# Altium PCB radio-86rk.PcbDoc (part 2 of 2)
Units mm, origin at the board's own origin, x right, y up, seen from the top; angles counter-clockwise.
Board outline 258 x 185 mm, 2 copper layers (Top Layer, Top, Bottom Layer, Bottom); 104 components, 185 nets, 870 pads, 319 vias.
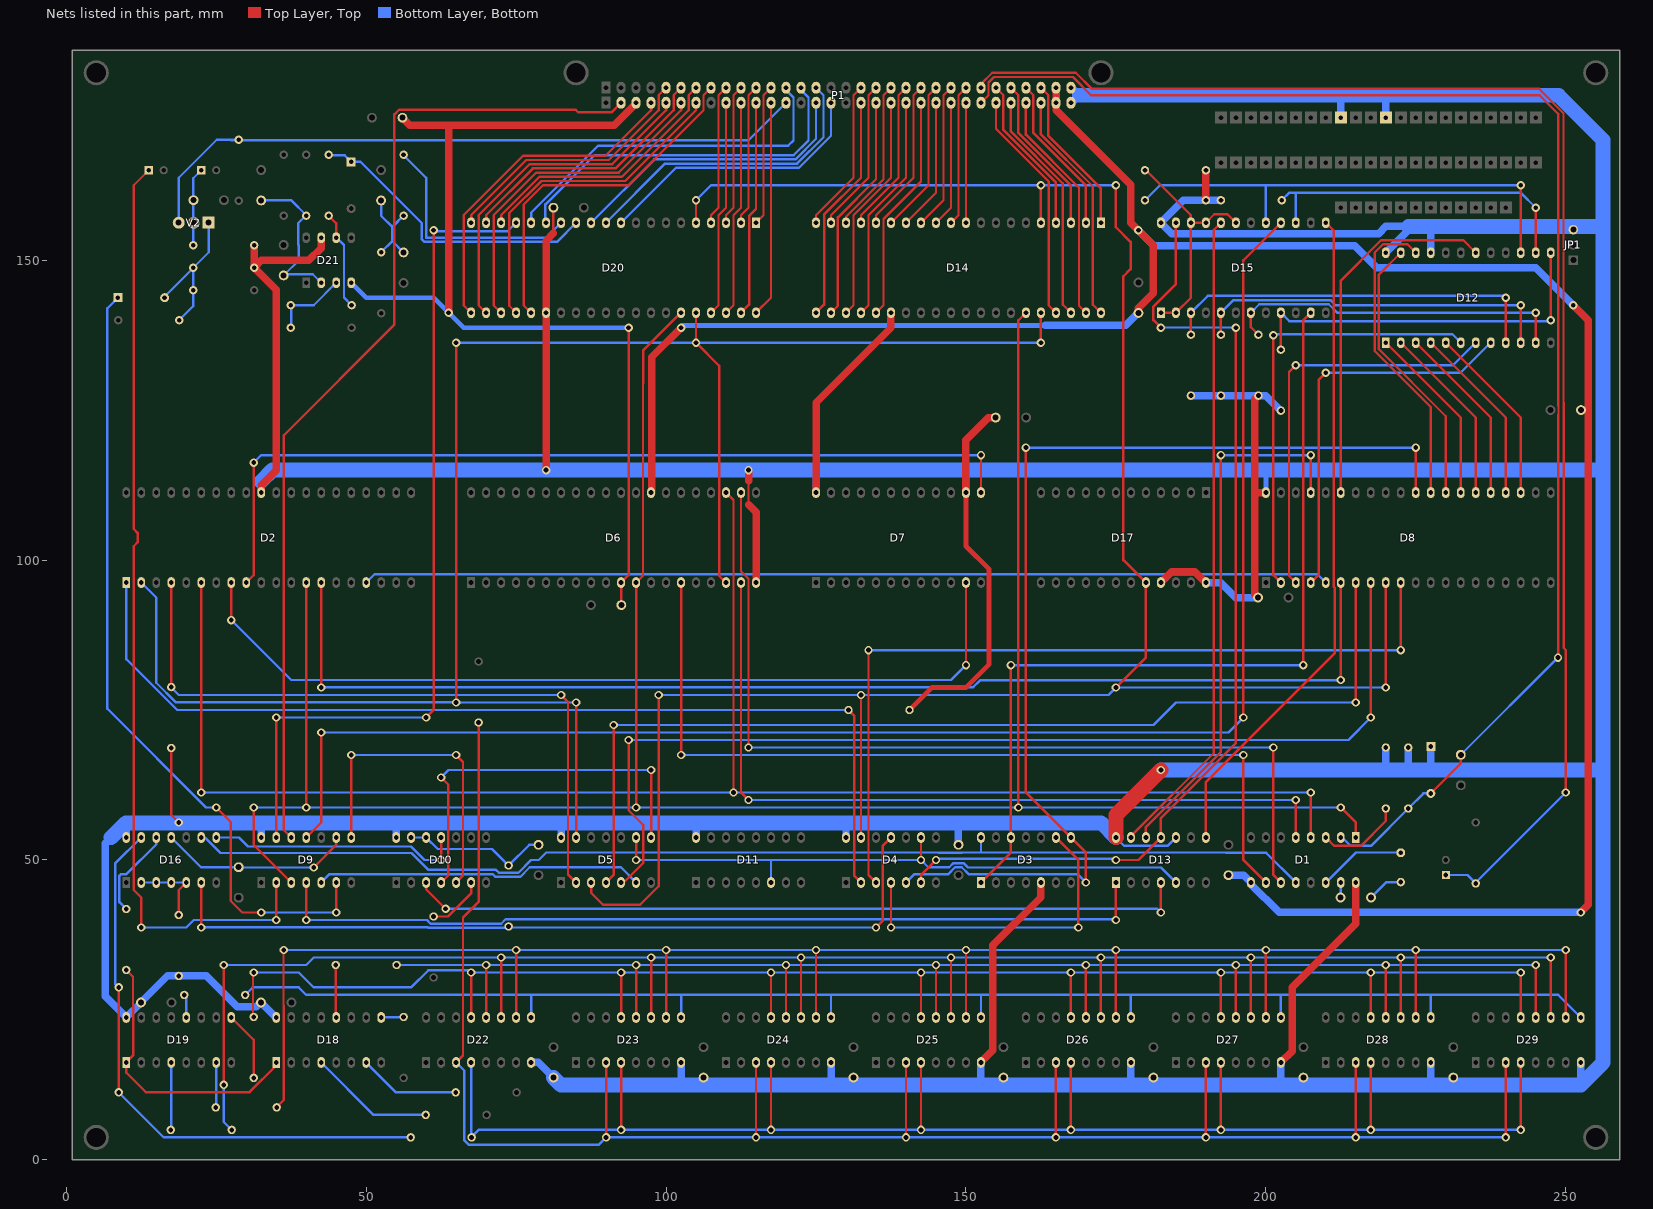
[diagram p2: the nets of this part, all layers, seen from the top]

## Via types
v1: diameter 1.4, hole 0.8, Top Layer, Top to Bottom Layer, Bottom, 318 vias
v2: diameter 1.4, hole 0.8, Top Layer, Top to Bottom Layer, Bottom, tented both sides, 1 vias

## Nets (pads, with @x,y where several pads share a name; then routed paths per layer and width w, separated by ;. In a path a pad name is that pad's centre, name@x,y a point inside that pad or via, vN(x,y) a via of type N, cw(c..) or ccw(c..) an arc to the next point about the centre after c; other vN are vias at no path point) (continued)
MA3: D22.12 D23.12 D24.12 D25.12 D26.12 D27.12 D28.12 D29.12 R24.1 | length 259.9
  Top Layer, Top w0.4: D22.12@70,23.75 v1(70,32.5) ; D23.12@95,23.75 v1(95,32.5) ; D24.12@120,23.75 v1(120,32.5) ; D25.12@145,23.75 v1(145,32.5) ; D26.12@170,23.75 v1(170,32.5) ; D27.12@195,23.75 v1(195,32.5) ; D28.12@220,23.75 v1(220,32.5) ; D29.12@245,23.75 v1(245,32.5)
  Bottom Layer, Bottom w0.4: R24.1@55.08,32.5 56.33,32.5 v1(70,32.5) v1(95,32.5) v1(120,32.5) v1(145,32.5) v1(170,32.5) v1(195,32.5) v1(220,32.5) v1(245,32.5)
MA4: D22.11 D23.11 D24.11 D25.11 D26.11 D27.11 D28.11 D29.11 R25.1 | length 329.8
  Top Layer, Top w0.4: v1(26.25,12.5) v1(26.25,32.5) ; D22.11@72.5,23.75 v1(72.5,33.75) ; D23.11@97.5,23.75 v1(97.5,33.75) ; D24.11@122.5,23.75 v1(122.5,33.75) ; D25.11@147.5,23.75 v1(147.5,33.75) ; D26.11@172.5,23.75 v1(172.5,33.75) ; D27.11@197.5,23.75 v1(197.5,33.75) ; D28.11@222.5,23.75 v1(222.5,33.75) ; D29.11@247.5,23.75 v1(247.5,33.75)
  Bottom Layer, Bottom w0.4: v1(26.25,12.5) 26.25,6.33 R25.1@27.58,5 ; v1(26.25,32.5) 40,32.5 41.25,33.75 v1(72.5,33.75) v1(97.5,33.75) v1(122.5,33.75) v1(147.5,33.75) v1(172.5,33.75) v1(197.5,33.75) v1(222.5,33.75) v1(247.5,33.75)
MA5: D22.10 D23.10 D24.10 D25.10 D26.10 D27.10 D28.10 D29.10 R26.1 | length 330.5
  Top Layer, Top w0.4: R26.1@35,8.75 36.25,10 36.25,25.666 36.215,25.701 36.215,34.965 v1(36.25,35) ; D22.10@75,23.75 v1(75,35) ; D23.10@100,23.75 v1(100,35) ; D24.10@125,23.75 v1(125,35) ; D25.10@150,23.75 v1(150,35) ; D26.10@175,23.75 v1(175,35) ; D27.10@200,23.75 v1(200,35) ; D28.10@225,23.75 v1(225,35) ; D29.10@250,23.75 v1(250,35)
  Bottom Layer, Bottom w0.4: v1(36.25,35) v1(75,35) v1(100,35) v1(125,35) v1(150,35) v1(175,35) v1(200,35) v1(225,35) v1(250,35)
MA6: D22.13 D23.13 D24.13 D25.13 D26.13 D27.13 D28.13 D29.13 R27.1 | length 281.2
  Top Layer, Top w0.4: R27.1@31.25,23.75 R27.1@31.25,23.83 31.135,23.945 31.135,31.135 v1(31.25,31.25) ; D22.13@67.5,23.75 v1(67.5,31.25) ; D23.13@92.5,23.75 v1(92.5,31.25) ; D24.13@117.5,23.75 v1(117.5,31.25) ; D25.13@142.5,23.75 v1(142.5,31.25) ; D26.13@167.5,23.75 v1(167.5,31.25) ; D27.13@192.5,23.75 v1(192.5,31.25) ; D28.13@217.5,23.75 v1(217.5,31.25) ; D29.13@242.5,23.75 v1(242.5,31.25)
  Bottom Layer, Bottom w0.4: v1(31.25,31.25) 38.75,31.25 41.25,28.75 57.501,28.75 60.371,31.62 67.13,31.62 v1(67.5,31.25) v1(92.5,31.25) v1(117.5,31.25) v1(142.5,31.25) v1(167.5,31.25) v1(192.5,31.25) v1(217.5,31.25) v1(242.5,31.25)
MA7: D22.9 D23.9 D24.9 D25.9 D26.9 D27.9 D28.9 D29.9 R34.1 | length 251.5
  Bottom Layer, Bottom w0.4: R34.1@29.83,27.5 31.08,28.75 38.749,28.75 40,27.499 77.5,27.499 ; D22.9@77.5,23.75 77.5,27.499 ; D23.9@102.5,23.75 102.5,27.499 ; D24.9@127.5,23.75 127.5,27.499 ; D25.9@152.5,23.75 152.5,27.499 ; D26.9@177.5,23.75 177.5,27.499 ; D27.9@202.5,23.75 202.5,27.499 ; D28.9@227.5,23.75 227.5,27.499 ; D29.9@252.5,23.75 248.751,27.499 227.5,27.499 ; 77.5,27.499 127.5,27.499 ; 127.5,27.499 152.5,27.499 ; 152.5,27.499 177.5,27.499 ; 177.5,27.499 202.5,27.499 ; 202.5,27.499 227.5,27.499
NetC3_1: C3.1 C4.2 R18.2 V2.C | length 13.1
  Bottom Layer, Bottom w0.4: R18.2@21.17,152.5 21.17,163.67 C3.1@22.5,165
NetC5_1: C5.1 C6.2 D21.2 R30.2 | length 26.8
  Bottom Layer, Bottom w0.4: C6.2@32.5,159.96 37.54,159.96 40,157.5 38.69,156.19 38.69,152.56 38.75,152.5 38.75,149.96 C5.1@36.44,147.65 ; C5.1@36.25,147.46 C5.1@36.44,147.65 ; D21.2@42.46,146.21 D21.2@42.48,146.19 ; D21.2@42.5,146.25 41.1,147.65 C5.1@36.44,147.65
NetC7_2: C7.2 C8.2 R32.2 R33.2 | length 18.2
  Bottom Layer, Bottom w0.4: R33.2@52.5,151.33 54.375,153.205 ; C8.2@52.5,159.96 52.5,157.42 54.375,155.545 ; 54.375,155.625 R32.2@56.25,157.5 ; C7.2@56.25,151.29 54.375,153.165 54.375,153.205 ; R32.2@56.25,157.42 54.375,155.545 ; 54.375,153.205 54.375,155.545
NetC26_1: C26.1 D9.2 | length 157.6
  Top Layer, Top w0.4: v1(12.5,38.75) 12.5,43.75 11.25,45 11.25,102.313 11.9,102.963 11.9,104.537 11.25,105.187 11.25,162.5 C26.1@13.75,165 ; v1(35,40) D9.2@35,46.25
  Bottom Layer, Bottom w0.4: v1(12.5,38.75) 20,38.75 21.25,40 v1(35,40)
NetC27_1: C27.1 D9.9 D16.11 | length 32.4
  Top Layer, Top w0.4: v1(41.25,48.75) 45,52.5 D9.9@45,53.75
  Bottom Layer, Bottom w0.4: D16.11@17.5,53.75 22.46,48.79 C27.1@28.75,48.79 28.79,48.75 v1(41.25,48.75)
NetC28_1: C28.1 D1.15 | length 2.5
  Bottom Layer, Bottom w0.4: C28.1@212.46,43.75 212.5,43.79 D1.15@212.5,46.25
NetC28_2: C28.2 Z1.2 | length 6
  Bottom Layer, Bottom w0.4: C28.2@217.54,43.75 220.1,46.31 Z1.2@222.5,46.31
NetC29_1: C29.1 D10.12 D10.13 R38.2 | length 24.6
  Bottom Layer, Bottom w0.4: D10.13@57.5,53.75 D10.12@60,53.75 61.925,51.825 71.005,51.825 R38.2@73.75,49.08 77.21,52.54 C29.1@78.75,52.54
NetD1_3: D1.3 R3.2 | length 14.6
  Top Layer, Top w0.4: D1.3@210,53.75 211.4,52.35 215.857,52.35 220,56.493 R3.2@220,58.59 R3.2@220,58.75
NetD1_10: D1.10 D6.15 | length 145.3
  Top Layer, Top w0.4: v1(102.5,67.5) D6.15@102.5,96.25 ; v1(196.25,67.5) 196.25,50 D1.10@200,46.25
  Bottom Layer, Bottom w0.4: v1(102.5,67.5) v1(196.25,67.5)
NetD1_11: D1.11 D6.22 | length 153.5
  Top Layer, Top w0.4: D6.22@112.5,111.25 112.5,98.126 113.75,96.876 v1(113.75,68.75) ; v1(201.25,68.75) 201.25,47.5 D1.11@202.5,46.25
  Bottom Layer, Bottom w0.4: v1(113.75,68.75) v1(201.25,68.75)
NetD1_14: D1.14 Z1.1 | length 14.5
  Bottom Layer, Bottom w0.4: D1.14@210,46.25 214.94,51.19 ; 215,51.25 Z1.1@222.5,51.25
NetD2_1: D2.1 D4.2 R4.2 | length 166.6
  Top Layer, Top w0.4: R4.2@130,75 R4.2@130.21,74.79 ; R4.2@130.42,75 131.35,74.07 131.35,47.4 D4.2@132.5,46.25
  Bottom Layer, Bottom w0.4: D2.1@10,96.25 10,83.499 18.499,75 R4.2@130.42,75
NetD2_4: D2.4 D5.2 R5.2 | length 115.3
  Top Layer, Top w0.4: R5.2@17.5,78.75 D2.4@17.5,96.25 ; v1(82.5,77.5) 83.65,76.35 83.65,47.6 D5.2@85,46.25
  Bottom Layer, Bottom w0.4: R5.2@17.5,78.75 18.75,77.5 v1(82.5,77.5)
NetD2_8: D2.8 D7.11 | length 147.7
  Top Layer, Top w0.4: v1(27.5,90) D2.8@27.5,96.25 ; v1(150,82.5) D7.11@150,96.25
  Bottom Layer, Bottom w0.4: v1(27.5,90) 37.5,80 147.5,80 v1(150,82.5)
NetD2_9: D2.9 D7.13 | length 148.5
  Top Layer, Top w0.4: D2.9@30,96.25 31.25,97.5 v1(31.25,116.25) ; D7.13@152.5,111.25 v1(152.5,117.5)
  Bottom Layer, Bottom w0.4: v1(31.25,116.25) 32.5,117.5 v1(152.5,117.5)
NetD2_14: D2.14 D8.6 | length 204.3
  Top Layer, Top w0.4: v1(42.5,78.75) D2.14@42.5,96.25 ; v1(212.5,80) D8.6@212.5,96.25
  Bottom Layer, Bottom w0.4: v1(42.5,78.75) 42.574,78.824 151.225,78.824 152.351,79.95 212.45,79.95 v1(212.5,80)
NetD2_17: D2.17 D8.5 | length 161.2
  Bottom Layer, Bottom w0.4: D2.17@50,96.25 51.4,97.65 208.6,97.65 D8.5@210,96.25
NetD3_8: D3.8 D4.5 D8.30 | length 181.2
  Top Layer, Top w0.4: v1(160,118.75) 160,61.25 D3.8@167.5,53.75 170,51.25 v1(170,46.25) ; D8.30@225,111.25 v1(225,118.75)
  Bottom Layer, Bottom w0.4: D4.5@140,46.25 141.4,47.65 147.066,47.65 148.201,48.785 149.299,48.785 150.434,47.65 168.6,47.65 v1(170,46.25) ; v1(160,118.75) v1(225,118.75)
NetD3_9: D3.9 D4.4 | length 55.3
  Top Layer, Top w0.4: v1(137.5,38.75) D4.4@137.5,46.25 ; D3.9@165,53.75 168.75,50 v1(168.75,38.75)
  Bottom Layer, Bottom w0.4: v1(137.5,38.75) v1(168.75,38.75)
NetD4_3: D4.3 D8.10 | length 139.3
  Top Layer, Top w0.4: v1(133.75,85) 133.75,47.5 D4.3@135,46.25 ; v1(222.5,85) D8.10@222.5,96.25
  Bottom Layer, Bottom w0.4: v1(133.75,85) v1(222.5,85)
NetD4_6: D4.6 D13.11 D15.23 | length 166.3
  Top Layer, Top w0.4: D4.6@142.5,46.25 142.5,47.5 v1(145,50) ; v1(175,50) 178.75,50 D13.11@182.5,53.75 182.5,57.003 195,69.503 v1(195,138.75) ; v1(182.5,138.75) 181.25,140 181.25,142.257 185,146.007 D15.23@185,156.25
  Bottom Layer, Bottom w0.4: v1(145,50) 145.185,50.185 174.815,50.185 v1(175,50) ; v1(182.5,138.75) 182.53,138.78 194.97,138.78 v1(195,138.75)
NetD4_9: D4.9 D5.9 D11.6 D13.5 | length 103.4
  Top Layer, Top w0.4: v1(95,50) D5.9@95,53.75 ; v1(142.5,50) D4.9@142.5,53.75
  Bottom Layer, Bottom w0.4: v1(95,50) 117.5,50 ; D11.6@117.5,46.25 117.5,50 ; D13.5@185,46.25 182.5,48.75 150.324,48.75 149.589,49.485 147.911,49.485 147.211,48.785 143.715,48.785 v1(142.5,50) 117.5,50
NetD4_11: D4.11 D16.6 R38.1 | length 136.2
  Top Layer, Top w0.4: v1(22.5,38.75) D16.6@22.5,46.25 ; v1(135,38.75) 136.15,39.9 136.15,52.4 D4.11@137.5,53.75
  Bottom Layer, Bottom w0.4: v1(22.5,38.75) 22.55,38.8 60.223,38.8 60.343,38.68 73.51,38.68 R38.1@73.665,38.835 ; R38.1@73.75,38.92 73.92,38.75 v1(135,38.75)
NetD5_4: D5.4 D8.7 | length 172.1
  Top Layer, Top w0.4: D5.4@90,46.25 91.25,47.5 v1(91.25,72.5) ; v1(215,76.25) D8.7@215,96.25
  Bottom Layer, Bottom w0.4: v1(91.25,72.5) 181.25,72.5 185,76.25 v1(215,76.25)
NetD5_5: D5.5 D8.8 | length 174.4
  Top Layer, Top w0.4: D5.5@92.5,46.25 92.947,46.25 96.2,49.503 96.2,55.853 93.75,58.303 v1(93.75,70) ; v1(217.5,73.75) D8.8@217.5,96.25
  Bottom Layer, Bottom w0.4: v1(93.75,70) 213.75,70 v1(217.5,73.75)
NetD5_6: D5.6 D9.5 | length 55
  Bottom Layer, Bottom w0.4: D9.5@42.5,46.25 43.9,47.65 71.1,47.65 71.57,47.18 75.68,47.18 77.285,48.785 92.465,48.785 D5.6@95,46.25
NetD5_8: D5.8 D10.4 | length 65.3
  Top Layer, Top w0.4: D10.4@62.5,46.25 63.7,47.45 63.7,62.55 v1(62.5,63.75) ; D5.8@97.5,53.75 v1(97.5,65)
  Bottom Layer, Bottom w0.4: v1(62.5,63.75) 63.75,65 v1(97.5,65)
NetD8_2: D8.2 D12.6 | length 73.7
  Top Layer, Top w0.4: v1(201.25,137.5) 201.25,97.5 D8.2@202.5,96.25
  Bottom Layer, Bottom w0.4: v1(201.25,137.5) 201.4,137.65 231.1,137.65 D12.6@232.5,136.25
NetD8_3: D8.3 D12.7 | length 68.8
  Top Layer, Top w0.4: D8.3@205,96.25 203.85,97.4 203.85,131.35 v1(205,132.5)
  Bottom Layer, Bottom w0.4: v1(205,132.5) 231.25,132.5 D12.7@235,136.25
NetD8_4: D8.4 D12.8 | length 65.6
  Top Layer, Top w0.4: D8.4@207.5,96.25 208.85,97.6 208.85,130.1 v1(210,131.25)
  Bottom Layer, Bottom w0.4: v1(210,131.25) 232.5,131.25 D12.8@237.5,136.25
NetD8_23: D8.23 D12.5 | length 30.2
  Top Layer, Top w0.4: D12.5@230,136.25 242.5,123.75 D8.23@242.5,111.25
NetD8_24: D8.24 D12.4 | length 30.2
  Top Layer, Top w0.4: D12.4@227.5,136.25 240,123.75 D8.24@240,111.25
NetD8_25: D8.25 D12.3 | length 30.2
  Top Layer, Top w0.4: D12.3@225,136.25 237.5,123.75 D8.25@237.5,111.25
NetD8_26: D8.26 D12.2 | length 30.2
  Top Layer, Top w0.4: D12.2@222.5,136.25 235,123.75 D8.26@235,111.25
NetD8_27: D8.27 D12.1 | length 30.2
  Top Layer, Top w0.4: D12.1@220,136.25 232.5,123.75 D8.27@232.5,111.25
NetD8_28: D8.28 D12.23 | length 46.1
  Top Layer, Top w0.4: D12.23@222.5,151.25 218.85,147.6 218.85,135.143 230,123.993 D8.28@230,111.25
NetD8_29: D8.29 D12.22 | length 51.9
  Top Layer, Top w0.4: D12.22@225,151.25 223.6,152.65 219.524,152.65 218.15,151.276 218.15,134.853 227.5,125.503 D8.29@227.5,111.25
NetD8_35: D8.35 D12.18 | length 61.5
  Top Layer, Top w0.4: D8.35@212.5,111.25 212.5,146.616 219.234,153.35 232.9,153.35 D12.18@235,151.25
NetD8_37: D8.37 D13.12 | length 90.2
  Top Layer, Top w0.4: D13.12@180,53.75 180,55.493 192.5,67.993 v1(192.5,117.5) ; D8.37@207.5,111.25 v1(207.5,117.5)
  Bottom Layer, Bottom w0.4: v1(192.5,117.5) v1(207.5,117.5)
NetD9_4: D9.4 D13.1 | length 148.1
  Top Layer, Top w0.4: v1(40,40) D9.4@40,46.25 ; v1(175,40) D13.1@175,46.25
  Bottom Layer, Bottom w0.4: v1(40,40) 60.133,40 60.753,39.38 72.513,39.38 73.253,40.12 174.88,40.12 v1(175,40)
NetD9_8: D9.8 D10.5 | length 53.5
  Top Layer, Top w0.4: D9.8@47.5,53.75 v1(47.5,67.5) ; D10.5@65,46.25 66.15,47.4 66.15,66.35 v1(65,67.5)
  Bottom Layer, Bottom w0.4: v1(47.5,67.5) v1(65,67.5)
NetD9_11: D9.11 D15.16 | length 258.4
  Top Layer, Top w0.4: D9.11@40,53.75 42.5,56.25 v1(42.5,71.25) ; v1(196.25,73.75) 196.25,150 D15.16@202.5,156.25
  Bottom Layer, Bottom w0.4: v1(42.5,71.25) 193.75,71.25 v1(196.25,73.75)
NetD9_13: D9.13 D20.17 | length 141.2
  Top Layer, Top w0.4: D9.13@35,53.75 v1(35,73.75) ; v1(60,73.75) 61.25,75 v1(61.25,155)
  Bottom Layer, Bottom w0.4: v1(35,73.75) v1(60,73.75) ; v1(61.25,155) 61.4,154.85 73.6,154.85 D20.17@75,156.25
NetD10_3: D10.3 D13.4 | length 130.2
  Top Layer, Top w0.4: D10.3@60,46.25 60,45.124 v1(63.25,41.874) ; v1(182.5,41.25) D13.4@182.5,46.25
  Bottom Layer, Bottom w0.4: v1(63.25,41.874) 181.876,41.874 v1(182.5,41.25)
NetD10_6: D10.6 R28.2 | length 9.7
  Top Layer, Top w0.4: R28.2@61.25,40.58 63.653,40.58 67.5,44.427 D10.6@67.5,46.25
NetD10_11: D10.11 D16.8 | length 42.8
  Top Layer, Top w0.4: v1(62.5,50) D10.11@62.5,53.75
  Bottom Layer, Bottom w0.4: D16.8@25,53.75 28.773,53.75 30.273,52.25 57.463,52.25 59.713,50 v1(62.5,50)
NetD12_9: D12.9 D15.3 R6.1 | length 65
  Top Layer, Top w0.4: R6.1@187.5,137.58 D15.3@187.5,141.25 ; D12.9@240,136.25 v1(240,143.75)
  Bottom Layer, Bottom w0.4: D15.3@187.5,141.25 190.3,144.05 239.7,144.05 v1(240,143.75)
NetD12_10: D12.10 D15.5 R7.1 | length 61.1
  Top Layer, Top w0.4: R7.1@192.5,137.58 D15.5@192.5,141.25 ; D12.10@242.5,136.25 v1(242.5,142.5)
  Bottom Layer, Bottom w0.4: D15.5@192.5,141.25 194.6,143.35 210.766,143.35 211.616,142.5 v1(242.5,142.5)
NetD12_11: D12.11 D15.7 R8.1 | length 57.8
  Top Layer, Top w0.4: D15.7@197.5,141.25 197.5,138.83 R8.1@198.75,137.58 ; D12.11@245,136.25 v1(245,141.25)
  Bottom Layer, Bottom w0.4: D15.7@197.5,141.25 198.9,142.65 210.476,142.65 211.876,141.25 v1(245,141.25)
NetD12_13: D12.13 D15.9 R9.1 | length 63.1
  Top Layer, Top w0.4: R9.1@202.5,135 D15.9@202.5,141.25 ; v1(247.5,140) D12.13@247.5,151.25
  Bottom Layer, Bottom w0.4: D15.9@202.5,141.25 203.9,139.85 247.35,139.85 v1(247.5,140)
NetD12_14: D12.14 D15.15 R10.1 | length 56.3
  Top Layer, Top w0.4: D12.14@245,151.25 v1(245,158.75)
  Bottom Layer, Bottom w0.4: R10.1@202.66,160 203.886,161.226 205,161.226 ; D15.15@205,156.25 205,161.226 ; v1(245,158.75) 242.524,161.226 205,161.226
NetD12_15: D12.15 D15.17 R11.1 | length 81.2
  Top Layer, Top w0.4: D12.15@242.5,151.25 v1(242.5,162.5)
  Bottom Layer, Bottom w0.4: R11.1@179.84,160 182.34,162.5 182.5,162.5 v1(242.5,162.5) ; D15.17@200,156.25 200,162.5
NetD13_8: D13.8 D15.13 | length 112
  Top Layer, Top w0.4: D13.8@190,53.75 190,63 211.5,84.5 211.5,95.374 211.35,95.524 211.35,154.9 D15.13@210,156.25
NetD13_13: D13.13 D15.20 | length 108.7
  Top Layer, Top w0.4: D13.13@177.5,53.75 177.5,53.983 191.3,67.783 191.3,155.05 D15.20@192.5,156.25
NetD15_1: D15.1 D15.2 D15.19 D15.21 D15.22 R12.1 | length 39.1
  Top Layer, Top w0.4: R12.1@180,165 187.5,157.5 D15.22@187.5,156.25 ; D15.1@182.5,141.25 D15.2@185,141.25 187.5,143.75 D15.22@187.5,156.25 ; D15.19@195,156.25 193.6,157.65 191.4,157.65 D15.21@190,156.25 D15.22@187.5,156.25
NetD16_2: D16.2 D16.3 D16.4 D16.5 R13.2 | length 13.4
  Top Layer, Top w0.4: R13.2@18.75,40.83 18.75,45 D16.5@20,46.25
  Bottom Layer, Bottom w0.4: D16.2@12.5,46.25 D16.3@15,46.25 D16.4@17.5,46.25 D16.5@20,46.25
NetD16_12: D16.12 R35.2 | length 15.5
  Bottom Layer, Bottom w0.4: R35.2@10,41.83 8.85,42.98 8.85,47.357 9.143,47.65 10.04,47.65 15,52.61 D16.12@15,53.75
NetD16_13: D16.13 R20.2 | length 96.4
  Top Layer, Top w0.4: v1(8.75,11.25) v1(8.75,28.75)
  Bottom Layer, Bottom w0.4: v1(8.75,11.25) 16.25,3.75 R20.2@57.5,3.75 ; v1(8.75,28.75) 8.15,29.35 8.15,49.4 D16.13@12.5,53.75
NetD18_1: D18.1 D19.1 R35.1 | length 46.8
  Top Layer, Top w0.4: R35.1@10,31.67 11.135,30.535 11.135,25.701 11.15,25.686 11.15,17.4 D19.1@10,16.25 10,14.553 13.253,11.3 30.577,11.3 35,15.723 D18.1@35,16.25
NetD18_4: D18.4 R21.2 | length 21.1
  Bottom Layer, Bottom w0.4: D18.4@42.5,16.25 51.25,7.5 R21.2@60,7.5
NetD18_7: D18.7 R22.2 | length 17
  Bottom Layer, Bottom w0.4: D18.7@50,16.25 55,11.25 R22.2@64.92,11.25
NetD18_9: D18.9 R23.2 | length 3.8
  Bottom Layer, Bottom w0.4: D18.9@52.5,23.75 R23.2@56.25,23.75
NetD18_12: D18.12 R24.2 | length 8.8
  Top Layer, Top w0.4: R24.2@44.92,32.5 44.92,23.83 D18.12@45,23.75
NetD19_4: D19.4 R25.2 | length 21.3
  Bottom Layer, Bottom w0.4: R25.2@17.42,5 17.5,5.08 D19.4@17.5,16.25 17.5,6.25
NetD19_7: D19.7 R26.2 | length 7.5
  Bottom Layer, Bottom w0.4: R26.2@25,8.75 D19.7@25,16.25
NetD19_9: D19.9 R27.2 | length 11.6
  Top Layer, Top w0.4: D19.9@27.5,23.75 31.25,20 R27.2@31.25,13.75
NetD19_12: D19.12 R34.2 | length 3.9
  Bottom Layer, Bottom w0.4: R34.2@19.67,27.5 20,27.17 D19.12@20,23.75
NetD21_3: D21.3 R36.1 R37.2 | length 12.9
  Bottom Layer, Bottom w0.4: R37.2@37.42,142.5 R37.2@37.5,142.5 ; R36.1@37.5,138.75 R37.2@37.5,142.5 ; D21.3@45,146.25 41.25,142.5 R37.2@37.5,142.5
NetD21_6: D21.6 R31.1 R37.1 | length 16.6
  Top Layer, Top w0.4: R31.1@43.75,157.42 45,156.17 D21.6@45,153.75 ; R31.1@43.75,157.5 R31.1@43.79,157.46
  Bottom Layer, Bottom w0.4: D21.6@45.02,153.81 46.31,152.52 46.31,143.77 R37.1@47.58,142.5
NetR15_2: R15.2 R16.2 R17.1 V2.B V4.1 | length 25.2
  Bottom Layer, Bottom w0.4: V4.1@16.4,143.75 16.4,143.9 R17.1@21.17,148.67 ; R15.2@18.83,140 21.17,142.34 R16.2@21.17,145 R17.1@21.17,148.67 ; V2.B@23.75,156.25 23.75,151.33 R17.1@21.17,148.75 R17.1@21.17,148.67
OSC: D1.12 D3.14 D16.9 | length 190.9
  Bottom Layer, Bottom w0.4: D16.9@22.5,53.75 23.124,53.75 25.714,51.16 57.563,51.16 60.373,48.35 71.65,48.35 72.12,47.88 75.38,47.88 77.5,50 78.785,50 80.034,51.249 145.417,51.249 145.451,51.215 149.299,51.215 149.333,51.249 152.5,51.249 ; D3.14@152.5,53.75 152.5,51.249 ; D1.12@205,46.25 200.035,51.215 193.368,51.215 193.334,51.249 152.5,51.249
P0A0: D20.4 P1.A9 | length 23.5
  Top Layer, Top w0.4: D20.4@107.5,156.25 107.5,157.5 108.75,158.75 108.75,177.5 P1.A9@110,178.75
P0A1: D20.3 P1.A10 | length 24.5
  Top Layer, Top w0.4: 110,157.25 D20.3@110,156.25 110,157.5 111.25,158.75 111.25,177.5 P1.A10@112.5,178.75
P0A2: D20.2 P1.A11 | length 24.5
  Top Layer, Top w0.4: 112.5,157.25 D20.2@112.5,156.25 112.5,157.5 113.75,158.75 113.75,177.5 P1.A11@115,178.75
P0A3: D20.1 P1.A12 | length 23.5
  Top Layer, Top w0.4: D20.1@115,156.25 116.25,157.5 116.25,177.5 P1.A12@117.5,178.75
P0A4: D20.40 P1.B12 | length 36
  Top Layer, Top w0.4: D20.40@115,141.25 117.5,143.75 P1.B12@117.5,176.25
P0A5: D20.39 P1.B11 | length 36
  Top Layer, Top w0.4: D20.39@112.5,141.25 113.85,142.6 113.85,157.357 115,158.507 P1.B11@115,176.25
P0A6: D20.38 P1.B10 | length 36
  Top Layer, Top w0.4: D20.38@110,141.25 111.25,142.5 111.25,157.5 112.5,158.75 P1.B10@112.5,176.25
P0A7: D20.37 P1.B9 | length 36
  Top Layer, Top w0.4: D20.37@107.5,141.25 108.75,142.5 108.75,157.5 110,158.75 P1.B9@110,176.25
P0B0: D20.18 P1.A7 | length 44
  Top Layer, Top w0.4: D20.18@72.5,156.25 72.5,157.48 78.92,163.9 92.65,163.9 103.75,175 103.75,177.5 P1.A7@105,178.75
P0B1: D20.19 P1.A6 | length 44
  Top Layer, Top w0.4: D20.19@70,156.25 70,157.5 77.8,165.3 91.55,165.3 101.25,175 101.25,177.5 P1.A6@102.5,178.75
P0B2: D20.20 P1.A5 | length 44
  Top Layer, Top w0.4: D20.20@67.5,156.25 67.5,157.5 76.7,166.7 90.45,166.7 98.75,175 98.75,177.5 P1.A5@100,178.75
P0B3: D20.21 P1.B4 | length 56.5
  Top Layer, Top w0.4: D20.21@67.5,141.25 66.25,142.5 66.25,157.5 76.15,167.4 89.9,167.4 97.5,175 P1.B4@97.5,176.25
P0B4: D20.22 P1.B5 | length 56.5
  Top Layer, Top w0.4: D20.22@70,141.25 68.75,142.5 68.75,157.5 77.25,166 91,166 100,175 P1.B5@100,176.25
P0B5: D20.23 P1.B6 | length 56.5
  Top Layer, Top w0.4: D20.23@72.5,141.25 71.25,142.5 71.25,157.5 78.35,164.6 92.1,164.6 102.5,175 P1.B6@102.5,176.25
P0B6: D20.24 P1.B7 | length 56.6
  Top Layer, Top w0.4: D20.24@75,141.25 73.85,142.4 73.85,157.84 79.21,163.2 93.2,163.2 105,175 P1.B7@105,176.25
P0B7: D20.25 P1.A8 | length 59.3
  Top Layer, Top w0.4: D20.25@77.5,141.25 76.25,142.5 76.25,159.25 79.5,162.5 93.75,162.5 106.25,175 106.25,175.5 106.25,177.5 P1.A8@107.5,178.75
P0C1: D20.15 P1.A14 | length 60.7
  Bottom Layer, Bottom w0.4: D20.15@80,156.25 79.885,156.365 79.885,159.299 88.085,167.499 121.27,167.499 123.75,169.979 123.75,177.118 122.5,178.368 P1.A14@122.5,178.75
P0C2: D20.16 P1.A13 | length 59.7
  Bottom Layer, Bottom w0.4: D20.16@77.5,156.25 77.5,157.904 88.695,169.099 120.373,169.099 121.25,169.976 121.25,177.118 120,178.368 P1.A13@120,178.75
P0C5: D20.12 P1.B15 | length 49.3
  Bottom Layer, Bottom w0.4: D20.12@87.5,156.25 98.049,166.799 121.56,166.799 125,170.239 P1.B15@125,176.25
P0C6: D20.11 P1.A15 | length 50.9
  Bottom Layer, Bottom w0.4: D20.11@90,156.25 99.849,166.099 121.849,166.099 126.25,170.499 126.25,177.5 P1.A15@125,178.75
P0C7: D20.10 P1.B16 | length 46.5
  Bottom Layer, Bottom w0.4: D20.10@92.5,156.25 101.649,165.399 122.139,165.399 127.5,170.759 P1.B16@127.5,176.25
P1A0: D14.4 P1.A27 | length 26.6
  Top Layer, Top w0.4: P1.A27@155,178.75 156.25,177.5 156.25,171.72 165,162.97 D14.4@165,156.25
P1A1: D14.3 P1.A28 | length 26.6
  Top Layer, Top w0.4: P1.A28@157.5,178.75 158.75,177.5 158.75,171.2 167.5,162.45 D14.3@167.5,156.25
P1A2: D14.2 P1.A29 | length 26.6
  Top Layer, Top w0.4: P1.A29@160,178.75 161.25,177.5 161.25,171.227 170,162.477 D14.2@170,156.25
P1A3: D14.1 P1.A30 | length 26.6
  Top Layer, Top w0.4: P1.A30@162.5,178.75 163.75,177.5 163.75,170.707 172.5,161.957 D14.1@172.5,156.25
P1A4: D14.40 P1.B30 | length 39.1
  Top Layer, Top w0.4: P1.B30@162.5,176.25 162.5,170.967 171.15,162.317 171.15,142.6 D14.40@172.5,141.25
P1A5: D14.39 P1.B29 | length 39.1
  Top Layer, Top w0.4: P1.B29@160,176.25 160,170.94 168.85,162.09 168.85,142.4 D14.39@170,141.25
P1A6: D14.38 P1.B28 | length 39.1
  Top Layer, Top w0.4: P1.B28@157.5,176.25 157.5,171.46 166.15,162.81 166.15,142.6 D14.38@167.5,141.25
P1A7: D14.37 P1.B27 | length 39.1
  Top Layer, Top w0.4: P1.B27@155,176.25 155,171.909 163.8,163.109 163.8,142.45 D14.37@165,141.25
P1B0: D14.18 P1.A20 | length 25.6
  Top Layer, Top w0.4: D14.18@130,156.25 130,157.24 136.25,163.49 136.25,177.5 P1.A20@137.5,178.75
P1B1: D14.19 P1.A19 | length 25.6
  Top Layer, Top w0.4: D14.19@127.5,156.25 127.5,157.5 133.75,163.75 133.75,177.5 P1.A19@135,178.75
P1B2: D14.20 P1.A18 | length 25.6
  Top Layer, Top w0.4: D14.20@125,156.25 125,157.5 131.25,163.75 131.25,177.5 P1.A18@132.5,178.75
P1B3: D14.21 P1.B18 | length 38.1
  Top Layer, Top w0.4: D14.21@125,141.25 126.35,142.6 126.35,157.6 132.5,163.75 P1.B18@132.5,176.25
P1B4: D14.22 P1.B19 | length 38.1
  Top Layer, Top w0.4: D14.22@127.5,141.25 128.65,142.4 128.65,157.14 135,163.49 P1.B19@135,176.25
P1B5: D14.23 P1.B20 | length 38.1
  Top Layer, Top w0.4: D14.23@130,141.25 131.25,142.5 131.25,157.5 137.5,163.75 P1.B20@137.5,176.25
P1B6: D14.24 P1.B21 | length 38.1
  Top Layer, Top w0.4: D14.24@132.5,141.25 133.75,142.5 133.75,157.5 140,163.75 P1.B21@140,176.25
P1B7: D14.25 P1.B22 | length 38.1
  Top Layer, Top w0.4: D14.25@135,141.25 136.25,142.5 136.25,156.876 142.5,163.126 P1.B22@142.5,176.25
P1C0: D14.14 P1.B23 | length 22.1
  Top Layer, Top w0.4: D14.14@140,156.25 145,161.25 P1.B23@145,176.25
P1C1: D14.15 P1.A23 | length 25.6
  Top Layer, Top w0.4: D14.15@137.5,156.25 143.75,162.5 143.75,177.5 P1.A23@145,178.75
P1C2: D14.16 P1.A22 | length 25.6
  Top Layer, Top w0.4: D14.16@135,156.25 135,157.5 141.25,163.75 141.25,177.5 P1.A22@142.5,178.75
P1C3: D14.17 P1.A21 | length 25.6
  Top Layer, Top w0.4: D14.17@132.5,156.25 132.5,157.5 138.75,163.75 138.75,177.5 P1.A21@140,178.75
P1C4: D14.13 P1.A24 | length 24.6
  Top Layer, Top w0.4: D14.13@142.5,156.25 146.25,160 146.25,177.5 P1.A24@147.5,178.75
P1C5: D14.12 P1.B24 | length 21
  Top Layer, Top w0.4: D14.12@145,156.25 147.5,158.75 P1.B24@147.5,176.25
P1C6: D14.11 P1.A25 | length 23.5
  Top Layer, Top w0.4: D14.11@147.5,156.25 148.75,157.5 148.75,177.5 P1.A25@150,178.75
P1C7: D14.10 P1.B25 | length 20
  Top Layer, Top w0.4: D14.10@150,156.25 P1.B25@150,176.25
P\0\C\3\: D9.12 P1.B2 | length 167.7
  Top Layer, Top w0.4: D9.12@37.5,53.75 36.25,55 36.25,120.8 54.715,139.265 54.715,174.299 55.491,175.075 84.925,175.075 85.35,174.65 90.9,174.65 P1.B2@92.5,176.25
PCLK: D3.1 D3.12 D15.11 | length 146.3
  Top Layer, Top w0.4: D3.1@152.5,46.25 157.5,51.25 D3.12@157.5,53.75 v1(157.5,82.5) ; v1(206.25,82.5) 206.25,140 D15.11@207.5,141.25
  Bottom Layer, Bottom w0.4: v1(157.5,82.5) v1(206.25,82.5)
R\A\S\: D22.4 D23.4 D24.4 D25.4 D26.4 D27.4 D28.4 D29.4 R20.1 | length 266.8
  Top Layer, Top w0.4: v1(92.5,5) D23.4@92.5,16.25 ; v1(117.5,5) D24.4@117.5,16.25 ; v1(142.5,5) D25.4@142.5,16.25 ; v1(167.5,5) D26.4@167.5,16.25 ; v1(192.5,5) D27.4@192.5,16.25 ; v1(217.5,5) D28.4@217.5,16.25 ; v1(242.5,5) D29.4@242.5,16.25
  Bottom Layer, Bottom w0.4: D22.4@67.5,16.25 67.5,3.75 68.75,5 v1(92.5,5) v1(117.5,5) v1(142.5,5) v1(167.5,5) v1(192.5,5) v1(217.5,5) v1(242.5,5)
R\D\: D4.13 D5.3 D8.9 D14.5 D17.20 D20.5 | length 379.9
  Top Layer, Top w0.4: D5.3@87.5,46.25 87.5,44.549 89.5,42.549 95.675,42.549 98.75,45.624 v1(98.75,77.5) ; D20.5@105,156.25 v1(105,160) ; D4.13@132.5,53.75 v1(132.5,77.5) ; D14.5@162.5,156.25 v1(162.5,162.5) ; v1(175,78.75) 180,83.75 D17.20@180,96.25 176.25,100 176.25,147.313 177.45,148.513 177.45,153.05 175,155.5 v1(175,162.5) ; v1(220,78.75) D8.9@220,96.25
  Bottom Layer, Bottom w0.4: v1(98.75,77.5) v1(132.5,77.5) 173.75,77.5 v1(175,78.75) v1(220,78.75) ; v1(105,160) 107.5,162.5 v1(162.5,162.5) v1(175,162.5)
RDY: D1.4 D2.6 D6.23 | length 278
  Top Layer, Top w0.4: v1(22.5,61.25) D2.6@22.5,96.25 ; D6.23@110,111.25 111.25,110 v1(111.25,61.25) ; D1.4@207.5,53.75 v1(207.5,61.25)
  Bottom Layer, Bottom w0.4: v1(22.5,61.25) v1(111.25,61.25) v1(207.5,61.25)
RST: D1.1 D2.13 D6.12 D9.3 D14.35 D20.35 | length 408.6
  Top Layer, Top w0.4: v1(31.25,58.75) 31.25,52.5 D9.3@37.5,46.25 ; v1(40,58.75) D2.13@40,96.25 ; v1(95,58.75) D6.12@95,96.25 96.15,97.4 96.15,129.403 96.2,129.453 96.2,133.975 96.175,134 96.175,134.925 D20.35@102.5,141.25 ; v1(158.75,58.75) 158.715,58.75 158.715,139.965 D14.35@160,141.25 ; v1(212.5,58.75) 215,56.25 D1.1@215,53.75
  Bottom Layer, Bottom w0.4: v1(31.25,58.75) v1(95,58.75) v1(158.75,58.75) v1(212.5,58.75)
RSTBTN1: C2.2 D1.2 P1.B26 R1.1 V1.1 | length 243.2
  Top Layer, Top w0.4: P1.B26@152.5,176.25 153.75,177.5 153.75,179.618 154.682,180.55 167.818,180.55 170.868,177.5 245.638,177.5 248.75,174.388 248.75,125.75 248.785,125.715 248.785,124.215 ; V1.1@227.5,61.1 232.5,66.1 C2.2@232.5,67.54 ; v1@248.75,83.75 248.75,124.215
  Bottom Layer, Bottom w0.4: D1.2@212.5,53.75 212.743,53.75 214.143,52.35 217.51,52.35 R1.1@223.75,58.59 226.26,61.1 V1.1@227.5,61.1 ; C2.2@232.54,67.5 C2.2@232.5,67.54 v1(248.71,83.75)
RSTBTN2: C1.1 P1.A26 R2.2 | length 241.7
  Top Layer, Top w0.4: P1.A26@152.5,178.75 152.5,179.358 154.392,181.25 168.3,181.25 171,178.55 245.578,178.55 249.628,174.5 249.628,126.284 249.662,126.25 249.662,85.338 250,85 v1(250,61.25)
  Bottom Layer, Bottom w0.4: C1.1@230,47.5 233.59,47.5 R2.2@234.84,46.25 ; R2.2@235,46.09 R2.2@234.84,46.25 ; v1(250,61.25) 235,46.25 R2.2@234.84,46.25
SYNC: D1.5 D6.19 | length 134.3
  Top Layer, Top w0.4: D6.19@112.5,96.25 112.5,61.25 v1(113.75,60) ; D1.5@205,53.75 v1(205,60)
  Bottom Layer, Bottom w0.4: v1(113.75,60) v1(205,60)
TAPI: D20.13 R31.2 V3.2 | length 50.1
  Bottom Layer, Bottom w0.4: R31.2@43.75,167.5 46.4,167.5 V3.2@47.5,166.4 49.047,166.4 59.3,156.147 59.3,153.46 59.71,153.05 81.8,153.05 D20.13@85,156.25
TAPO: D20.14 R32.1 | length 38.8
  Bottom Layer, Bottom w0.4: R32.1@56.25,167.5 60,163.75 60,153.75 80,153.75 D20.14@82.5,156.25
VCC: C15.2 C16.2 C17.2 C18.2 C19.2 C20.2 C21.2 C22.2 C23.2 C24.2 C25.2 C30.2 C31.2 D1.16 D2.31 D3.5 D4.14 D5.14 D6.20 D7.14 D7.24 D8.40 D9.14 D10.14 D11.16 D12.21 D12.24 D13.10 D13.14 D14.26 D15.24 D16.14 D17.21 D17.24 D18.16 D19.16 D20.26 D21.7 D22.8 D23.8 D24.8 D25.8 D26.8 D27.8 D28.8 D29.8 JP1.3 P1.A32 P1.B32 pad.0@212.5,173.75 pad.0@220,173.75 R1.2 R3.1 R4.1 R5.1 R6.2 R7.2 R8.2 R9.2 R10.2 R11.2 R12.2 R13.1 R17.2 R18.1 V1.2 | length 1534.7
  Top Layer, Top w0.4: R5.1@17.5,68.75 17.5,57.5 v1(18.75,56.25) ; 81.21,154.46 C25.2@81.21,158.75 ; 113.75,109.25 113.75,113.25
  Top Layer, Top w0.8: R4.1@140.58,75 144.33,78.75 150,78.75 153.85,82.6 153.85,98.5 150,102.35 D7.14@150,111.25
  Top Layer, Top w1.25: R18.1@31.33,152.5 R17.2@31.33,148.75 ; D2.31@32.5,111.25 32.5,112.5 35,115 35,145.08 R17.2@31.33,148.75 ; D21.7@42.5,153.75 42.5,152 40.46,149.96 32.54,149.96 R17.2@31.33,148.75 ; v1(80,115) D20.26@80,141.25 80,153.25 81.21,154.46 ; 113.75,109.25 115,108 D6.20@115,96.25 ; 113.75,113.25 v1(113.75,115) ; D7.24@125,111.25 125,126.25 137.5,138.75 D14.26@137.5,141.25 ; D7.14@150,111.25 150,120 153.75,123.75 C15.2@154.19,123.75 ; D25.8@152.5,16.25 154.5,18.25 154.5,35.75 162.5,43.75 D3.5@162.5,46.25 ; D17.21@182.5,96.25 184.325,98.075 188.152,98.075 D17.24@189.977,96.25 ; R11.2@190,160 R12.2@190,165 ; C16.2@198.71,93.75 198.125,94.335 198.125,111.25 ; R8.2@198.75,127.42 198.125,126.795 198.125,111.25 ; D8.40@200,111.25 198.125,111.25 ; D27.8@202.5,16.25 204.375,18.125 204.375,28.75 215,39.375 D1.16@215,46.25
  Top Layer, Top w2.5: D13.14@175,53.75 175,57.5 v1(182.5,65)
  Bottom Layer, Bottom w0.4: D13.14@175,53.75 176.4,52.35 183.6,52.35 D13.10@185,53.75
  Bottom Layer, Bottom w0.8: D8.40@200,111.25 200,115
  Bottom Layer, Bottom w1.25: 7.5,53.75 6.5,52.75 6.5,27.25 D19.16@10,23.75 C30.2@12.46,26.21 ; D16.14@10,53.75 10,56.2 ; C30.2@12.46,26.25 16.88,30.67 R13.1@18.75,30.67 23.33,30.67 28.5,25.5 31.71,25.5 C31.2@32.46,26.25 34.96,23.75 D18.16@35,23.75 ; D9.14@32.5,53.75 32.5,56.2 ; D2.31@32.5,111.25 32.5,113.127 ; D10.14@55,53.75 55,56.2 ; D22.8@77.5,16.25 78.71,16.25 C17.2@81.25,13.71 ; D5.14@82.5,53.75 82.5,56.2 ; 102.5,12.5 D23.8@102.5,16.25 ; D11.16@105,53.75 105,56.2 ; D7.24@125,111.25 125,115 ; 127.5,12.5 D24.8@127.5,16.25 ; D4.14@130,53.75 130,56.2 ; C24.2@148.75,52.54 148.75,56.2 ; D7.14@150,111.25 150,114.996 ; 152.5,12.5 D25.8@152.5,16.25 ; P1.B32@167.5,176.25 167.643,176.25 168.892,177.499 167.641,178.75 P1.A32@167.5,178.75 ; 177.5,12.5 D26.8@177.5,16.25 ; R6.2@187.5,127.42 R8.2@198.75,127.42 200,127.42 R9.2@202.5,124.92 ; D17.24@190,96.25 192.496,96.25 194.996,93.75 C16.2@198.71,93.75 ; R10.2@192.5,160 R11.2@190,160 186.25,160 D15.24@182.5,156.25 184.325,154.425 218.8,154.425 220,155.625 223.75,155.625 223.75,155 D12.24@220,151.25 ; 202.5,12.5 D27.8@202.5,16.25 ; pad.0@212.5,173.75 212.5,177.499 ; 220,65 R3.1@220,68.75 ; pad.0@220,173.75 220,177.499 ; 223.75,65 R1.2@223.75,68.75 ; 227.5,12.5 D28.8@227.5,16.25 ; 227.5,65 V1.2@227.5,68.9 ; D12.21@227.5,151.25 227.5,155.625 ; 252.5,12.5 D29.8@252.5,16.25
  Bottom Layer, Bottom w2.5: 7.5,53.75 9.95,56.2 10,56.2 32.5,56.2 55,56.2 82.5,56.2 105,56.2 130,56.2 148.75,56.2 172.55,56.2 D13.14@175,53.75 ; 32.5,113.127 34.373,115 v1(80,115) v1(113.75,115) 125,115 200,115 256.25,115 ; C17.2@81.25,13.71 82.46,12.5 127.5,12.5 152.5,12.5 177.5,12.5 202.5,12.5 227.5,12.5 252.5,12.5 256.247,16.247 256.247,65 227.5,65 223.75,65 220,65 v1(182.5,65) ; 168.892,177.499 212.5,177.499 220,177.499 248.751,177.499 256.25,170 256.25,155.5 256.25,115 ; 223.75,155.625 227.5,155.625 255,155.625 ; 256.25,65.003 256.25,115
VDD: C11.2 C12.2 C13.2 D1.9 D6.28 P1.A31 P1.B31 | length 395
  Top Layer, Top w1.25: D6.28@97.575,111.25 97.575,133.825 v1(102.5,138.75) ; P1.A31@165,178.75 165.075,178.675 165.075,175.006 177.5,162.581 177.5,156.25 v1(178.75,155) 181.25,152.5 181.25,144.46 178.75,141.96 C13.2@178.75,141.21 ; v1(251.25,142.5) 253.75,140 253.75,125 ; v1(252.5,41.25) 253.75,42.5 253.75,125 ; C12.2@252.54,125 253.75,125
  Bottom Layer, Bottom w0.8: v1(102.5,138.75) 102.875,139.125 163.25,139.125
  Bottom Layer, Bottom w1.25: 163.25,139.125 176.665,139.125 C13.2@178.75,141.21 ; v1(178.75,155) 181.325,152.425 214.825,152.425 218.5,148.75 245,148.75 v1(251.25,142.5) ; C11.2@193.75,47.46 196.29,47.46 D1.9@197.5,46.25 ; D1.9@197.5,45.99 202.24,41.25 v1(252.5,41.25)
VOUT: P1.B13 R19.2 V2.E | length 115.2
  Bottom Layer, Bottom w0.4: V2.E@18.75,156.25 18.75,163.75 25.08,170.08 R19.2@28.75,170.08 ; 27.499,169.999 113.749,169.999 P1.B13@120,176.25
VSS: C9.2 C10.2 D6.11 D21.4 P1.B3 | length 168.5
  Top Layer, Top w0.4: C9.2@92.54,92.5 92.54,96.21 D6.11@92.5,96.25 93.75,97.5 v1(93.75,138.75)
  Top Layer, Top w1.25: C10.2@56.04,173.75 57.29,172.5 63.75,172.5 ; v1(63.75,141.25) 63.75,172.5 ; P1.B3@95,176.25 95,176.131 91.369,172.5 63.75,172.5
  Bottom Layer, Bottom w0.8: D21.4@47.5,146.25 50,143.75 61.25,143.75 v1(63.75,141.25) 66.25,138.75 v1(93.75,138.75)
VSYNC: D9.6 V4.2 | length 134.2
  Top Layer, Top w0.4: v1(25,58.75) 27.425,56.325 27.425,43.161 29.336,41.25 v1(32.5,41.25) ; v1(45,41.25) D9.6@45,46.25
  Bottom Layer, Bottom w0.4: V4.2@8.6,143.75 6.85,142 6.85,75.203 23.303,58.75 v1(25,58.75) ; v1(32.5,41.25) v1(45,41.25)
W\R\: D2.2 D5.13 D6.18 D14.36 D20.36 | length 321.2
  Top Layer, Top w0.4: v1(65,76.25) v1(65,136.25) ; D5.13@85,53.75 v1(85,76.25) ; D20.36@105,141.25 v1(105,136.25) 108.85,132.4 108.85,97.4 D6.18@110,96.25 ; v1(162.5,136.25) D14.36@162.5,141.25
  Bottom Layer, Bottom w0.4: D2.2@12.5,96.25 15,93.75 15,79.553 18.229,76.324 64.926,76.324 v1(65,76.25) v1(85,76.25) ; v1(65,136.25) v1(105,136.25) v1(162.5,136.25)
W\R\A\M\: D22.3 D23.3 D24.3 D25.3 D26.3 D27.3 D28.3 D29.3 R14.1 | length 333.7
  Top Layer, Top w0.4: D22.3@65,16.25 66.15,17.4 66.15,40.4 68.75,43 R14.1@68.75,72.92 ; v1(90,3.75) D23.3@90,16.25 ; v1(115,3.75) D24.3@115,16.25 ; v1(140,3.75) D25.3@140,16.25 ; v1(165,3.75) D26.3@165,16.25 ; v1(190,3.75) D27.3@190,16.25 ; v1(215,3.75) D28.3@215,16.25 ; v1(240,3.75) D29.3@240,16.25
  Bottom Layer, Bottom w0.4: D22.3@65,16.25 66.38,14.87 66.38,3.253 67.083,2.55 88.8,2.55 v1(90,3.75) v1(115,3.75) v1(140,3.75) v1(165,3.75) v1(190,3.75) v1(215,3.75) v1(240,3.75)
pads on no net: D1.7 D1.13 D2.3 D2.5 D2.15 D2.24 D2.25 D2.36 D3.2 D3.3 D3.4 D3.11 D3.13 D6.24 D7.23 D8.1 D8.11 D8.31 D8.32 D8.33 D8.34 D8.36 D8.38 D8.39 D10.8 D10.9 D10.10 D11.12 D11.13 D11.14 D11.15 D12.16 D12.17 D13.6 D13.9 D15.4 D15.6 D15.8 D15.10 D15.14 D15.18 D16.10 D21.1 D21.5 D21.8 D22.1 D23.1 D24.1 D25.1 D26.1 D27.1 D28.1 D29.1 P1.A16 P1.A17 P1.B8 P1.B17

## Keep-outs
Keep-Out Layer, Board:
  the board outline again, w0.14

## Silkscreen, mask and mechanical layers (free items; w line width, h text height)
Top Overlay:
  lines w0.2: 107.5,171.25 107.5,174.75 ; 127.5,171.25 127.5,174.75 ; 147.5,171.25 147.5,174.75 ; 221.016,60.622 221.016,66.718
  text "RADIO-86RK, rev. 1" at 11.25,181.25 h1.5
  text "maddev*xlat, 2015" at 224.5,181.25 h1.5
  text "A1" at 79.25,178.249 h1.5
  text "A32" at 176.5,178.25 h1.5
  text "B1" at 79.25,175.75 h1.5
  text "B32" at 176.5,175.75 h1.5
  text "8" at 107,169.25 h1.5
  text "16" at 126.75,169.25 h1.5
  text "24" at 146.5,169.25 h1.5
  text "H" at 252,157 h1.5 r90
  text "CHR A10" at 254.75,148.25 h1.5 r90
  text "L" at 252,147.25 h1.5 r90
